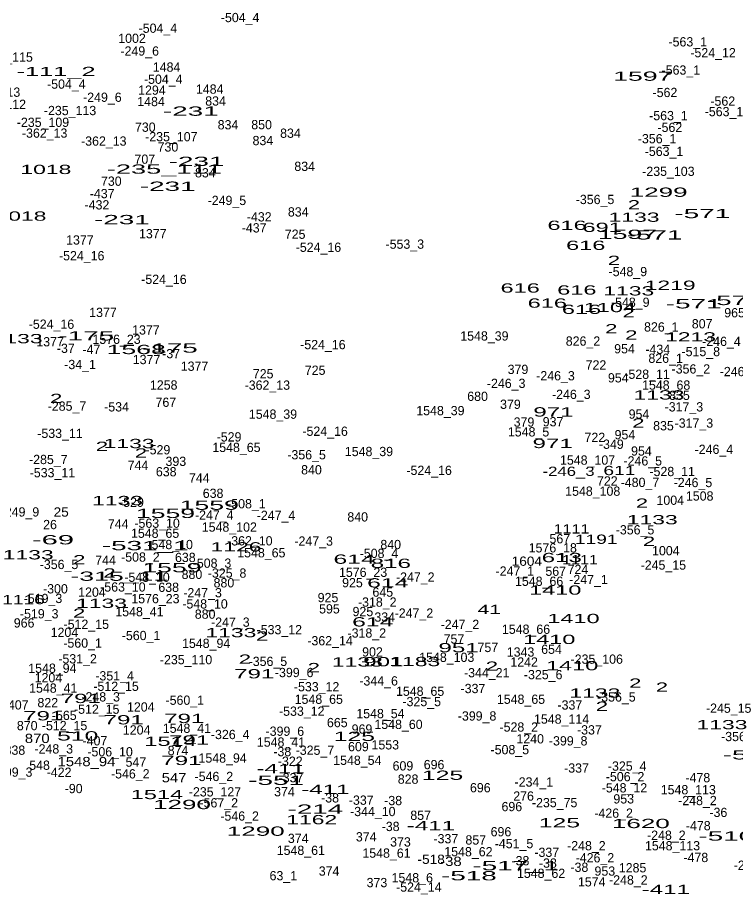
# Model space of a CAD drawing. Extents: x -660434 to -656144, y -997850 to -994016.
# Drawn here: x -659014.2 to -658704, y -995568.7 to -995192.7 of the extents above; entities that cross this region are included whole.
import ezdxf
from ezdxf.enums import TextEntityAlignment as Align

# ---------------------------------------------------------------- set-up
doc = ezdxf.new("R2010")
doc.units = 0
doc.header["$LTSCALE"] = 1.6
doc.layers.add('24', color=7, linetype='Continuous')

msp = doc.modelspace()

# ---------------------------------------------------------------- texts
at = {"layer": '24'}
for s, p in [('-504_4', (-658918.015, -995194.73)), ('-504_4', (-658953.545, -995199.34)), ('1002', (-658964.718, -995203.7)), ('-563_1', (-658724.632, -995205.23)), ('-235_115', (-659018.869, -995211.82)), ('-249_6', (-658961.398, -995209.19)), ('-524_12', (-658713.709, -995209.92)), ('1484', (-658949.779, -995216.13)), ('-563_1', (-658727.612, -995217.43)), ('-504_4', (-658993.095, -995223.49)), ('-504_4', (-658951.235, -995221.38)), ('-362_13', (-659022.811, -995226.98)), ('1294', (-658956.13, -995226.1)), ('1484', (-658931.159, -995225.64)), ('-562', (-658734.49, -995227.11)), ('-249_6', (-658977.528, -995229.17)), ('1484', (-658956.499, -995231.02)), ('834', (-658928.631, -995230.79)), ('-562', (-658709.52, -995230.85)), ('-235_112', (-659021.809, -995232.23)), ('-235_113', (-658991.489, -995234.91)), ('-563_1', (-658732.982, -995237.1)), ('-563_1', (-658708.982, -995235.37)), ('-235_109', (-659003.195, -995240)), ('730', (-658958.997, -995242.1)), ('834', (-658923.251, -995241.06)), ('850', (-658908.741, -995241.01)), ('-562', (-658732.37, -995242.19)), ('-362_13', (-659002.461, -995244.66)), ('834', (-658896.281, -995244.71)), ('-362_13', (-658976.921, -995248.11)), ('-235_107', (-658947.745, -995246.21)), ('834', (-658908.181, -995247.88)), ('-356_1', (-658737.882, -995247.08)), ('730', (-658949.197, -995250.64)), ('-563_1', (-658734.902, -995252.56)), ('707', (-658959.182, -995255.92)), ('834', (-658890.131, -995259.02)), ('-235_103', (-658732.999, -995261.18)), ('834', (-658933.041, -995261.81)), ('730', (-658973.667, -995265.43)), ('-437', (-658977.625, -995270.81)), ('-432', (-658979.869, -995275.67)), ('-249_5', (-658923.732, -995273.76)), ('-356_5', (-658764.698, -995273.34)), ('834', (-658892.921, -995278.71)), ('-432', (-658909.779, -995280.85)), ('-437', (-658911.965, -995285.6)), ('1377', (-658987.241, -995290.83)), ('1377', (-658955.751, -995288.14)), ('725', (-658894.243, -995288.35)), ('-524_16', (-658884.175, -995293.98)), ('-553_3', (-658846.872, -995292.64)), ('-524_16', (-658986.455, -995297.65)), ('-548_9', (-658750.522, -995304.5)), ('-524_16', (-658950.935, -995307.83)), ('-548_9', (-658749.472, -995317.75)), ('1377', (-658977.261, -995322.14)), ('965', (-658704.408, -995322.28)), ('-524_16', (-658999.515, -995327.23)), ('826_1', (-658736.074, -995328.4)), ('807', (-658718.427, -995327.05)), ('1377', (-658958.721, -995329.72)), ('1548_39', (-658812.487, -995332.3)), ('1377', (-659000.111, -995334.82)), ('1576_23', (-658971.409, -995333.75)), ('-524_16', (-658882.255, -995336.04)), ('826_2', (-658769.9, -995334.52)), ('-246_4', (-658710.076, -995334.64)), ('-37', (-658993.321, -995337.65)), ('-47', (-658982.265, -995338.14)), ('-37', (-658947.811, -995339.95)), ('954', (-658751.957, -995337.84)), ('-434', (-658737.593, -995338.08)), ('-515_8', (-658719.006, -995339.05)), ('1377', (-658958.441, -995342.5)), ('826_1', (-658734.194, -995341.94)), ('-34_1', (-658987.17, -995344.65)), ('1377', (-658937.701, -995345.38)), ('725', (-658885.603, -995347.12)), ('379', (-658797.988, -995346.75)), ('722', (-658764.283, -995344.83)), ('-356_2', (-658723.298, -995346.56)), ('725', (-658908.063, -995348.66)), ('-246_3', (-658781.772, -995349.51)), ('954', (-658754.657, -995350.4)), ('-528_11', (-658742.219, -995348.85)), ('-246_4', (-658702.496, -995347.69)), ('1258', (-658951.03, -995353.5)), ('-362_13', (-658906.261, -995353.56)), ('-246_3', (-658803.082, -995352.78)), ('1548_68', (-658733.957, -995353.54)), ('680', (-658815.427, -995358.39)), ('-246_3', (-658774.952, -995357.55)), ('835', (-658728.207, -995357.95)), ('-285_7', (-658992.818, -995362.63)), ('767', (-658950.093, -995360.96)), ('379', (-658801.248, -995361.83)), ('-534', (-658971.399, -995362.94)), ('1548_39', (-658903.827, -995366.1)), ('1548_39', (-658831.497, -995364.57)), ('954', (-658745.707, -995366.07)), ('-317_3', (-658726.312, -995362.94)), ('379', (-658795.388, -995369.51)), ('937', (-658782.828, -995369.38)), ('-317_3', (-658721.992, -995369.96)), ('-524_16', (-658881.295, -995373.47)), ('1548_5', (-658793.413, -995373.74)), ('835', (-658735.127, -995371.11)), ('-533_11', (-658995.839, -995374.4)), ('-529', (-658922.81, -995375.92)), ('722', (-658764.773, -995376.14)), ('954', (-658751.787, -995374.98)), ('-529', (-658953.53, -995381.49)), ('1548_65', (-658919.607, -995380.47)), ('-349', (-658757.655, -995379.09)), ('-246_4', (-658713.346, -995381.29)), ('-356_5', (-658889.308, -995383.64)), ('1548_39', (-658862.357, -995382.24)), ('954', (-658744.657, -995382.01)), ('-285_7', (-659000.878, -995385.68)), ('744', (-658962.141, -995388.19)), ('393', (-658945.783, -995386.48)), ('1548_107', (-658767.915, -995385.94)), ('-246_5', (-658744.082, -995386.3)), ('-533_11', (-658999.109, -995391.4)), ('638', (-658949.943, -995390.97)), ('840', (-658887.195, -995390.13)), ('-524_16', (-658836.365, -995390.37)), ('-528_11', (-658731.369, -995390.88)), ('744', (-658935.651, -995393.66)), ('722', (-658759.393, -995394.95)), ('-480_7', (-658745.286, -995395.59)), ('-246_5', (-658722.392, -995395.63)), ('638', (-658929.693, -995400.29)), ('1548_108', (-658765.69, -995399.37)), ('1004', (-658732.192, -995403.29)), ('1508', (-658719.484, -995401.46)), ('-529', (-658964.95, -995404.16)), ('-508_1', (-658915.3, -995404.81)), ('-249_9', (-659013.138, -995408.34)), ('-247_4', (-658929.196, -995409.71)), ('-247_4', (-658902.506, -995409.82)), ('840', (-658867.225, -995410.49)), ('26', (-659000.133, -995413.8)), ('744', (-658970.691, -995413.54)), ('-563_10', (-658953.885, -995413.21)), ('1548_102', (-658922.68, -995414.89)), ('1548_65', (-658954.737, -995417.54)), ('-356_5', (-658747.418, -995416.07)), ('-548_10', (-658948.243, -995422.43)), ('-362_10', (-658913.825, -995420.83)), ('-247_3', (-658886.252, -995420.93)), ('840', (-658852.965, -995422.43)), ('567', (-658779.908, -995419.93)), ('1548_65', (-658908.847, -995425.99)), ('-508_4', (-658858.031, -995426.25)), ('1576_18', (-658782.953, -995423.86)), ('1004', (-658734.112, -995425.09)), ('744', (-658976.161, -995429.2)), ('-508_2', (-658961.106, -995427.83)), ('638', (-658941.693, -995428)), ('-356_5', (-658996.268, -995431.04)), ('-508_3', (-658930.166, -995430.48)), ('-247_1', (-658799.346, -995433.91)), ('567', (-658781.678, -995433.96)), ('724', (-658772.077, -995433.19)), ('-245_15', (-658735.179, -995431.29)), ('-548_10', (-658958.243, -995436.55)), ('880', (-658938.831, -995435.32)), ('-325_8', (-658923.652, -995434.76)), ('1576_23', (-658864.889, -995434.41)), ('-247_2', (-658842.362, -995436.49)), ('-247_1', (-658767.506, -995437.56)), ('-300', (-658997.813, -995441.56)), ('-563_10', (-658968.665, -995440.77)), ('638', (-658948.883, -995440.91)), ('880', (-658925.021, -995438.96)), ('925', (-658869.493, -995438.91)), ('1548_66', (-658788.843, -995438.29)), ('1204', (-658982.028, -995443)), ('-247_3', (-658934.242, -995443.25)), ('925', (-658880.053, -995445.35)), ('645', (-658856.387, -995442.99)), ('-519_3', (-659003.192, -995445.72)), ('1576_23', (-658954.609, -995445.81)), ('-548_10', (-658933.183, -995448.08)), ('-318_2', (-658858.776, -995447.3)), ('-519_3', (-659004.822, -995452.35)), ('1548_41', (-658961.521, -995451.43)), ('880', (-658933.131, -995452.5)), ('595', (-658879.433, -995450.22)), ('925', (-658864.983, -995451.39)), ('-247_2', (-658842.942, -995452.05)), ('966', (-659011.333, -995456.3)), ('-247_3', (-658922.242, -995455.97)), ('-334', (-658856.439, -995453.77)), ('1204', (-658993.918, -995460.37)), ('-512_15', (-658984.479, -995456.88)), ('-533_12', (-658901.085, -995459.2)), ('-247_2', (-658823.062, -995456.94)), ('1548_66', (-658794.503, -995459.03)), ('-560_1', (-658960.816, -995461.74)), ('-362_14', (-658879.175, -995463.99)), ('-318_2', (-658863.286, -995460.65)), ('757', (-658825.639, -995463.25)), ('-560_1', (-658986.076, -995465)), ('1548_94', (-658932.692, -995465.12)), ('757', (-658810.999, -995466.9)), ('654', (-658783.497, -995467.68)), ('902', (-658860.837, -995468.83)), ('1548_103', (-658828.74, -995471.15)), ('1343', (-658796.874, -995468.87)), ('-531_2', (-658988.246, -995471.81)), ('-235_110', (-658941.383, -995472.17)), ('-356_5', (-658906.018, -995472.92)), ('1242', (-658795.324, -995473.18)), ('-235_106', (-658763.955, -995471.95)), ('1548_94', (-658999.122, -995475.88)), ('-351_4', (-658972.25, -995479.16)), ('-399_6', (-658894.668, -995477.73)), ('-344_21', (-658811.484, -995477.82)), ('-325_6', (-658787.098, -995478.64)), ('1204', (-659000.828, -995479.97)), ('-344_6', (-658858.186, -995481.35)), ('1548_41', (-658998.761, -995484.46)), ('-512_15', (-658971.609, -995483.68)), ('-533_12', (-658884.965, -995483.87)), ('1548_65', (-658840.257, -995485.81)), ('-337', (-658817.431, -995484.64)), ('-248_3', (-658978.267, -995488.25)), ('-560_1', (-658941.916, -995489.68)), ('1548_65', (-658884.037, -995489.27)), ('-325_5', (-658839.562, -995490.28)), ('1548_65', (-658796.677, -995489.27)), ('-356_5', (-658755.478, -995488.29)), ('-407', (-659014.769, -995491.72)), ('822', (-659001.107, -995490.74)), ('-512_15', (-658979.959, -995493.57)), ('1204', (-658960.938, -995492.6)), ('-337', (-658775.571, -995491.75)), ('-245_15', (-658706.949, -995493.14)), ('-565', (-658994, -995496.25)), ('-533_12', (-658891.395, -995494.44)), ('1548_54', (-658857.407, -995495.47)), ('-399_8', (-658815.653, -995496.5)), ('1548_114', (-658779.144, -995497.85)), ('870', (-659009.997, -995500.67)), ('-512_15', (-658993.859, -995500.66)), ('1548_41', (-658941.021, -995501.8)), ('665', (-658876.048, -995499.36)), ('1548_60', (-658849.591, -995500.14)), ('-528_2', (-658797.632, -995501.27)), ('1204', (-658962.718, -995502.53)), ('-326_4', (-658922.312, -995504.51)), ('-399_6', (-658898.698, -995503.09)), ('969', (-658865.373, -995502.16)), ('-337', (-658767.121, -995502.51)), ('-356_5', (-658701.908, -995505.39)), ('-407', (-658980.739, -995507.23)), ('1548_41', (-658900.371, -995507.79)), ('1553', (-658855.31, -995508.97)), ('1240', (-658792.708, -995506.38)), ('-399_8', (-658776.293, -995507.25)), ('838', (-659015.317, -995511.28)), ('-248_3', (-658998.527, -995510.73)), ('-506_10', (-658974.199, -995511.98)), ('874', (-658944.837, -995511.41)), ('-38', (-658899.805, -995511.91)), ('-325_7', (-658885.698, -995511.3)), ('609', (-658866.922, -995509.75)), ('-508_5', (-658801.506, -995511.05)), ('547', (-658963.037, -995516.44)), ('1548_94', (-658925.582, -995514.68)), ('-322', (-658896.365, -995516.06)), ('1548_54', (-658867.387, -995515.64)), ('548', (-659004.651, -995517.78)), ('609', (-658847.682, -995518.06)), ('696', (-658834.233, -995517.51)), ('-337', (-658772.691, -995519)), ('-325_4', (-658750.817, -995518.16)), ('-99_3', (-659014.593, -995520.77)), ('-422', (-658996.219, -995520.82)), ('-546_2', (-658965.472, -995521.5)), ('-546_2', (-658929.372, -995522.64)), ('-337', (-658896.041, -995523.18)), ('828', (-658845.447, -995523.79)), ('-506_2', (-658751.712, -995522.72)), ('-478', (-658720.285, -995523.16)), ('-90', (-658989.934, -995527.87)), ('696', (-658814.263, -995527.5)), ('-234_1', (-658791.12, -995525.02)), ('-548_12', (-658751.979, -995527.55)), ('-235_127', (-658928.891, -995529.29)), ('374', (-658898.877, -995529.23)), ('-38', (-658879.165, -995531.89)), ('276', (-658795.568, -995531.1)), ('1548_113', (-658724.41, -995528.37)), ('-567_2', (-658927.244, -995534.03)), ('-337', (-658865.701, -995532.88)), ('-38', (-658851.905, -995533.05)), ('696', (-658800.633, -995535.66)), ('-235_75', (-658782.137, -995533.95)), ('953', (-658752.303, -995532.32)), ('-248_2', (-658720.447, -995533.05)), ('-344_10', (-658860.698, -995537.79)), ('857', (-658840.033, -995539.41)), ('-426_2', (-658756.672, -995538.49)), ('-36', (-658711.41, -995538.17)), ('-546_2', (-658918.242, -995539.74)), ('-38', (-658852.995, -995544.24)), ('696', (-658805.333, -995546.52)), ('-478', (-658720.095, -995543.9)), ('374', (-658892.927, -995549.39)), ('374', (-658863.547, -995548.72)), ('-337', (-658829.141, -995549.54)), ('857', (-658816.213, -995550.07)), ('-248_2', (-658733.887, -995548.03)), ('373', (-658848.743, -995550.92)), ('-451_5', (-658799.7, -995551.65)), ('-248_2', (-658768.437, -995552.55)), ('1548_113', (-658731.22, -995552.57)), ('1548_61', (-658891.791, -995554.56)), ('1548_61', (-658854.781, -995555.76)), ('1548_62', (-658819.397, -995555.15)), ('-337', (-658785.551, -995555.41)), ('-426_2', (-658764.732, -995557.78)), ('-478', (-658721.155, -995557.64)), ('-38', (-658796.925, -995559.03)), ('-38', (-658785.065, -995560.07)), ('-38', (-658771.455, -995561.87)), ('-235_123', (-658693.465, -995561)), ('63_1', (-658899.344, -995565.52)), ('374', (-658879.587, -995563.51)), ('1548_62', (-658788.007, -995564.48)), ('953', (-658760.463, -995563.53)), ('1285', (-658748.47, -995562.1)), ('373', (-658858.913, -995568.49)), ('1548_6', (-658843.658, -995566.4)), ('1574', (-658766.12, -995568.17)), ('-248_2', (-658750.297, -995567.34)), ('-524_14', (-658840.814, -995570.43))]:
    msp.add_text(s, height=4, dxfattribs=at).set_placement(p, align=Align.CENTER)
for s, width, p in [('-111_2', 2.05, (-658997.534, -995218.05)), ('1597', 2.15, (-658744.057, -995220.06)), ('-231', 2.25, (-658939.331, -995235.17)), ('-231', 2.25, (-658936.821, -995256.87)), ('1018', 1.85, (-659001.94, -995260.36)), ('-235_111', 2.2, (-658950.774, -995260.21)), ('-231', 2.25, (-658949.301, -995267.62)), ('1299', 2.1, (-658737.217, -995270.2)), ('2', 1.8, (-658747.891, -995275.63)), ('-571', 2.25, (-658718.345, -995279.42)), ('1018', 1.85, (-659012.69, -995280.52)), ('-231', 2.25, (-658969.081, -995282.03)), ('1133', 1.85, (-658747.814, -995280.99)), ('616', 1.9, (-658776.767, -995284.49)), ('691', 1.9, (-658761.637, -995285.39)), ('1597', 2.15, (-658750.687, -995288.39)), ('-571', 2.25, (-658738.985, -995288.64)), ('616', 1.9, (-658768.707, -995293.14)), ('2', 1.8, (-658756.531, -995299.64)), ('616', 1.9, (-658797.027, -995311.58)), ('616', 1.9, (-658772.547, -995312.44)), ('1133', 1.85, (-658750.114, -995312.82)), ('1219', 1.85, (-658732.249, -995310.4)), ('-571', 2.25, (-658704.325, -995316.97)), ('616', 1.9, (-658785.317, -995318.11)), ('616', 1.9, (-658770.527, -995320.8)), ('1104', 1.9, (-658758.266, -995320.03)), ('-571', 2.25, (-658722.085, -995318.41)), ('2', 1.8, (-658750.191, -995322.29)), ('-175', 2.25, (-658984.475, -995332.26)), ('2', 1.8, (-658757.681, -995329.19)), ('2', 1.8, (-658749.041, -995331.89)), ('1133', 1.85, (-659014.364, -995333.46)), ('1213', 1.85, (-658723.414, -995332.71)), ('1568', 2.15, (-658962.913, -995338.15)), ('-175', 2.25, (-658948.375, -995337.55)), ('1133', 1.85, (-658737.064, -995357.78)), ('2', 1.8, (-658997.501, -995359.31)), ('971', 1.95, (-658782.657, -995365.12)), ('2', 1.8, (-658745.971, -995369.91)), ('2', 1.8, (-658977.721, -995379.99)), ('1133', 1.85, (-658965.974, -995378.79)), ('971', 1.95, (-658782.997, -995378.76)), ('2', 1.8, (-658960.831, -995382.87)), ('-246_3', 1.35, (-658776.13, -995390.78)), ('611', 1.55, (-658754.159, -995390.44)), ('1133', 1.85, (-658970.964, -995403.43)), ('1559', 2.15, (-658931.343, -995405.43)), ('2', 1.8, (-658744.431, -995404.56)), ('25', 1.1, (-658995.319, -995408.38)), ('1559', 2.15, (-658950.253, -995408.98)), ('1133', 1.85, (-658739.994, -995411.69)), ('1111', 1.3, (-658774.837, -995415.67)), ('-69', 2.35, (-658998.863, -995420.37)), ('1191', 1.55, (-658764.185, -995420.14)), ('2', 1.8, (-658741.361, -995421.04)), ('-531_1', 2.25, (-658959.017, -995422.88)), ('1126', 1.85, (-658919.799, -995423.44)), ('1133', 1.85, (-659009.564, -995426.86)), ('2', 1.8, (-658987.521, -995428.97)), ('614', 2, (-658868.758, -995428.75)), ('1604', 1.1, (-658794.16, -995429.63)), ('613', 1.95, (-658779.053, -995428.05)), ('1111', 1.3, (-658771.187, -995428.97)), ('1559', 2.15, (-658947.473, -995432.42)), ('816', 1.95, (-658852.913, -995430.54)), ('-315_11', 2.15, (-658970.214, -995436.11)), ('2', 1.8, (-658974.461, -995434.71)), ('614', 2, (-658854.218, -995438.98)), ('1410', 1.9, (-658781.896, -995442.1)), ('1116', 1.55, (-659011.615, -995446.21)), ('1133', 1.85, (-658977.884, -995447.8)), ('2', 1.8, (-658987.601, -995452.08)), ('41', 1.7, (-658810.403, -995450.47)), ('614', 2, (-658860.698, -995455.83)), ('1410', 1.9, (-658774.016, -995454.39)), ('1133', 1.85, (-658922.004, -995460.48)), ('2', 1.8, (-658908.471, -995461.97)), ('1410', 1.9, (-658784.486, -995463.42)), ('951', 1.95, (-658823.643, -995467.01)), ('2', 1.8, (-658915.951, -995471.95)), ('1133', 1.85, (-658867.374, -995473.15)), ('901', 1.95, (-658856.149, -995473.06)), ('1183', 1.85, (-658842.564, -995472.99)), ('2', 1.8, (-658809.251, -995475)), ('1410', 1.9, (-658774.596, -995474.75)), ('791', 1.95, (-658911.917, -995478.27)), ('2', 1.8, (-658886.191, -995475.6)), ('2', 1.8, (-658747.311, -995482.31)), ('1133', 1.85, (-658764.764, -995486.6)), ('2', 1.8, (-658735.791, -995484.04)), ('791', 1.95, (-658986.847, -995488.93)), ('2', 1.8, (-658761.711, -995492.3)), ('791', 1.95, (-659003.077, -995496.42)), ('791', 1.95, (-658942.157, -995497.57)), ('791', 1.95, (-658968.317, -995498.15)), ('1133', 1.85, (-658709.854, -995500.24)), ('510', 2, (-658988.174, -995505.11)), ('125', 2, (-658868.677, -995505.3)), ('870', 1.2, (-659005.67, -995506.19)), ('1514', 1.9, (-658948.079, -995507.44)), ('791', 1.95, (-658940.037, -995506.89)), ('1548_94', 1.2, (-658984.39, -995516.21)), ('791', 1.95, (-658943.397, -995515.72)), ('-510', 2.25, (-658697.527, -995513.29)), ('-411', 1.95, (-658900.532, -995519.25)), ('547', 1.2, (-658946.54, -995523.17)), ('-551', 2.25, (-658902.461, -995524.29)), ('125', 2, (-658830.557, -995522.11)), ('1514', 1.9, (-658953.959, -995530.44)), ('-411', 1.95, (-658881.192, -995528.23)), ('1290', 2.1, (-658943.149, -995534.76)), ('-214', 2.25, (-658885.506, -995536.76)), ('1162', 1.85, (-658887.089, -995541.29)), ('125', 2, (-658780.087, -995542.66)), ('1620', 2.1, (-658744.899, -995542.96)), ('1290', 2.1, (-658911.269, -995546.28)), ('-411', 1.95, (-658835.592, -995543.88)), ('-510', 2.25, (-658707.987, -995548.39)), ('-518', 1.1, (-658835.481, -995558.42)), ('-38', 1.2, (-658826.95, -995559.32)), ('-517_1', 2.25, (-658798.953, -995561.21)), ('-518', 2.25, (-658819.191, -995565.53)), ('-411', 1.95, (-658734.082, -995571.44))]:
    msp.add_text(s, height=4, dxfattribs=dict(at, width=width)).set_placement(p, align=Align.CENTER)

doc.saveas('drawing.dxf')
